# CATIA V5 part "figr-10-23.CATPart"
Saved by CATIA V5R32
Part number: Part1
Bounding box of the stored display mesh (mm): x -174.518 to 0, y -36.805 to 36.805, z 0 to 36.805
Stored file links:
  D:\PROJECTS\Project 2022\CATIA V5 6R 2022\Resources\Part Files\c10_catia_v5_6r2022_prt\c10_catia_v5_6r2022_prt\figr-10-23.CATPart
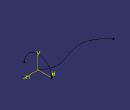
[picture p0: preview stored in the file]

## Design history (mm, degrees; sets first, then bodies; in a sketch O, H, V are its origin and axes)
Body1 (main body)
  Sketch1 on xy-plane, origin (0, 0, 0), H (1, 0, 0), V (0, 1, 0)
    spline S1 through (0, 0) (-31.5913, 14.7273) (-94.8038, 0) (-174.5181, 29.5113)
    point P1 (0, 0)
    point P2 (-94.8038, 0)
    coincidence: P1 O, P2 H
  Sketch2 on yz-plane, origin (0, 0, 0), H (0, 1, 0), V (0, 0, 1)
    arc A1 centre (0, 0) radius 36.8048 from (36.8048, 0) to (-36.8048, 0) ccw
    point P1 (-36.8048, 0)
    point P2 (36.8048, 0)
    coincidence: P1 H, P2 H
